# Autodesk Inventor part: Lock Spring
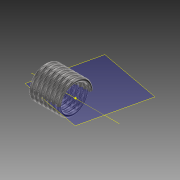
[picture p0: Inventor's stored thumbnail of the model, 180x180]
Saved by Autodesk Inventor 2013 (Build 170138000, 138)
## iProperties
Created: 2009-03
Part Number: Lock Spring
Document SubType Name: Modeling
Designer: tangg
Density: 7.84 g/cm^3
Material: Steel, High Strength Low Alloy
Mass: 2.03542 g
Surface Area: 8.33252 cm^2
Volume: 0.25962 cm^3
Author: tangg
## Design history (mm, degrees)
sketch "Sketch1"
  geometry: 1 further point
sketch "3D Sketch1"
  node "Helical Curve1" dims "d0" = 10.238, "d1" = 70, "d2" = 9.609, "d3" = 0
workplane "Work Plane1"
sketch "Sketch2"
  geometry: C1 r 0.625 at (0, 0); 1 further point
  constraints: 1 centre point
  dimensions: "d5" = 1.25 diameter of C1
sweep "Sweep1" sketch "Sketch2" dims "d4" = 0
body "Solid1"
